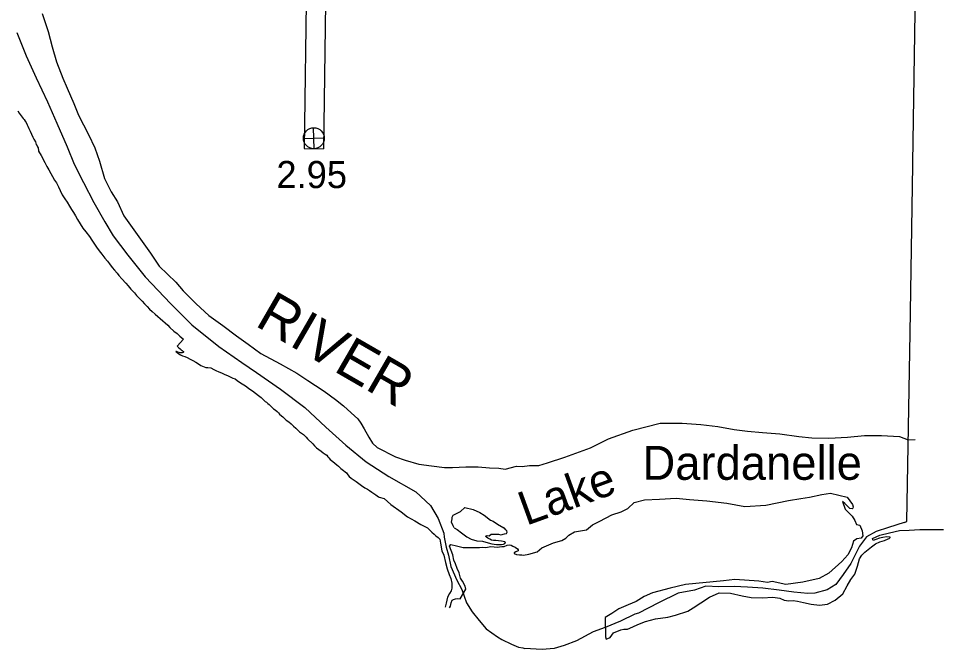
# Model space of a CAD drawing. Extents: x -939622 to -934245, y 1383184 to 1385301.
# Drawn here: x -936165.29 to -936122.1, y 1384575.76 to 1384605.22 of the extents above; entities that cross this region are included whole.
import ezdxf

# ---------------------------------------------------------------- set-up
doc = ezdxf.new("R2010")
doc.units = 0
for name, color, linetype in [('Level 10', 7, 'Continuous'), ('Level 2', 7, 'Continuous'), ('Level 25', 7, 'Continuous'), ('Level 26', 7, 'Continuous'), ('Level 9', 7, 'Continuous')]:
    doc.layers.add(name, color=color, linetype=linetype)

msp = doc.modelspace()

# ---------------------------------------------------------------- linework, layer by layer
at = {"layer": 'Level 10'}
for points in [[(-936149.7, 1384613.496), (-936150.055, 1384613.37), (-936150.212, 1384613.233), (-936150.433, 1384613.002), (-936150.766, 1384612.565), (-936151.072, 1384612.074), (-936151.171, 1384611.898), (-936151.238, 1384611.699), (-936151.269, 1384611.558), (-936151.633, 1384609.156), (-936151.818, 1384608.195), (-936151.844, 1384607.955), (-936151.836, 1384607.099), (-936151.951, 1384599.154)], [(-936149.134, 1384612.628), (-936149.592, 1384612.579), (-936149.748, 1384612.416), (-936150.025, 1384612.053), (-936150.297, 1384611.615), (-936150.345, 1384611.53), (-936150.37, 1384611.457), (-936150.384, 1384611.393), (-936150.745, 1384609.003), (-936150.927, 1384608.06), (-936150.944, 1384607.911), (-936150.936, 1384607.097), (-936151.051, 1384599.14)], [(-936151.951, 1384599.154), (-936151.051, 1384599.14)]]:
    msp.add_lwpolyline(points, dxfattribs=at)
at = {"layer": 'Level 2'}
for points in [[(-936123.81, 1384581.739), (-936123.664, 1384590.549), (-936123.533, 1384598.366), (-936123.535, 1384598.481), (-936123.408, 1384606.518), (-936123.297, 1384614.414), (-936123.256, 1384617.539)], [(-936165.368, 1384604.569), (-936164.93, 1384603.475), (-936164.453, 1384602.443), (-936163.928, 1384601.334), (-936163.498, 1384600.338), (-936163.015, 1384599.229), (-936162.681, 1384598.417), (-936162.252, 1384597.554), (-936161.768, 1384596.621), (-936161.249, 1384595.725), (-936160.86, 1384595.078), (-936160.182, 1384594.169), (-936159.375, 1384593.158), (-936158.176, 1384591.902), (-936157.186, 1384590.92), (-936155.932, 1384589.908), (-936154.864, 1384589.151), (-936154.175, 1384588.684), (-936153.047, 1384587.915), (-936151.919, 1384587.059), (-936150.937, 1384586.146), (-936150.001, 1384585.306), (-936149.047, 1384584.522), (-936147.993, 1384583.841), (-936146.73, 1384583.12), (-936146.057, 1384582.475), (-936145.698, 1384581.882), (-936145.426, 1384581.189)], [(-936123.934, 1384581.692), (-936124.663, 1384581.454), (-936125.24, 1384581.274), (-936125.704, 1384581.017), (-936126.016, 1384580.585), (-936126.421, 1384579.775), (-936126.785, 1384579.255), (-936127.123, 1384578.79), (-936127.525, 1384578.546), (-936128.114, 1384578.396), (-936128.44, 1384578.381), (-936129.096, 1384578.44), (-936129.766, 1384578.523), (-936130.539, 1384578.616), (-936131.245, 1384578.668), (-936131.879, 1384578.707), (-936132.595, 1384578.68), (-936133.19, 1384578.716), (-936133.731, 1384578.53), (-936134.494, 1384578.395), (-936135.411, 1384577.932), (-936136.337, 1384577.452), (-936136.508, 1384577.407), (-936137.175, 1384577.084), (-936137.9, 1384576.781), (-936138.461, 1384576.585), (-936139.241, 1384576.17), (-936139.811, 1384575.945), (-936140.274, 1384575.814), (-936140.832, 1384575.76), (-936141.658, 1384575.814)], [(-936123.934, 1384581.692), (-936123.81, 1384581.739)], [(-936145.52, 1384581.438), (-936145.426, 1384581.189), (-936145.408, 1384581.012), (-936145.317, 1384580.537), (-936145.217, 1384580.165), (-936145.105, 1384579.637), (-936144.822, 1384579.004), (-936144.593, 1384578.56), (-936144.364, 1384577.936), (-936144.103, 1384577.516), (-936143.784, 1384577.115), (-936143.45, 1384576.731), (-936142.928, 1384576.354), (-936142.715, 1384576.22), (-936142.276, 1384576.008), (-936141.94, 1384575.867), (-936141.739, 1384575.832), (-936141.658, 1384575.814)]]:
    msp.add_lwpolyline(points, dxfattribs=at)
at = {"layer": 'Level 26'}
for p, q in [((-936151.487, 1384599.14), (-936151.509, 1384600.117)), ((-936151.986, 1384599.617), (-936151.01, 1384599.64))]:
    msp.add_line(p, q, dxfattribs=at)
msp.add_circle((-936151.498, 1384599.628), 0.488, dxfattribs=at)
at = {"layer": 'Level 9'}
for points in [[(-936164.182, 1384605.455), (-936163.899, 1384604.604), (-936163.712, 1384603.898), (-936163.507, 1384603.189), (-936163.221, 1384602.431), (-936163.012, 1384601.962), (-936162.696, 1384601.246), (-936162.484, 1384600.705), (-936162.016, 1384599.797), (-936161.714, 1384599.174), (-936161.497, 1384598.555), (-936161.265, 1384597.755), (-936160.961, 1384597.133), (-936160.659, 1384596.654), (-936160.361, 1384596.005), (-936159.904, 1384595.358), (-936159.13, 1384594.268), (-936158.711, 1384593.655), (-936157.934, 1384592.902), (-936157.593, 1384592.501), (-936156.992, 1384591.89), (-936156.402, 1384591.351), (-936155.741, 1384590.881), (-936155.113, 1384590.398), (-936154.568, 1384590.009), (-936153.978, 1384589.581), (-936153.068, 1384589.089), (-936152.299, 1384588.658), (-936151.781, 1384588.314), (-936151.416, 1384588.082), (-936151.009, 1384587.82), (-936150.488, 1384587.431), (-936150.117, 1384587.138), (-936149.749, 1384586.804), (-936149.45, 1384586.521), (-936149.303, 1384586.331), (-936149.151, 1384586.061), (-936148.927, 1384585.666), (-936148.757, 1384585.393), (-936148.536, 1384585.197), (-936147.685, 1384584.747), (-936147.23, 1384584.599), (-936146.592, 1384584.417), (-936146.007, 1384584.334), (-936145.402, 1384584.255), (-936145.024, 1384584.263), (-936144.407, 1384584.294), (-936143.822, 1384584.281), (-936143.289, 1384584.24), (-936142.854, 1384584.224), (-936142.561, 1384584.181), (-936142.042, 1384584.321), (-936141.772, 1384584.308)], [(-936165.314, 1384600.907), (-936165.247, 1384600.792), (-936165.164, 1384600.674), (-936165.119, 1384600.616), (-936165.072, 1384600.556), (-936165.028, 1384600.498), (-936164.975, 1384600.422), (-936164.933, 1384600.356), (-936164.886, 1384600.25)], [(-936164.886, 1384600.25), (-936164.857, 1384600.19), (-936164.81, 1384600.081), (-936164.746, 1384599.954), (-936164.684, 1384599.818), (-936164.617, 1384599.685), (-936164.564, 1384599.589), (-936164.499, 1384599.453), (-936164.453, 1384599.338), (-936164.42, 1384599.28), (-936164.397, 1384599.229), (-936164.373, 1384599.172), (-936164.365, 1384599.136), (-936164.356, 1384599.096), (-936164.354, 1384599.063), (-936164.351, 1384599.021), (-936164.233, 1384598.822), (-936164.057, 1384598.492), (-936163.96, 1384598.314), (-936163.872, 1384598.154), (-936163.78, 1384597.987), (-936163.701, 1384597.845), (-936163.601, 1384597.676), (-936163.512, 1384597.543), (-936163.415, 1384597.355), (-936163.345, 1384597.189), (-936163.239, 1384596.99), (-936163.121, 1384596.805), (-936163.018, 1384596.636), (-936162.909, 1384596.463), (-936162.809, 1384596.297), (-936162.718, 1384596.155), (-936162.623, 1384596.009), (-936162.529, 1384595.834), (-936162.408, 1384595.628), (-936162.275, 1384595.435), (-936162.142, 1384595.256), (-936161.971, 1384595.041), (-936161.865, 1384594.865), (-936161.776, 1384594.735), (-936161.64, 1384594.538), (-936161.516, 1384594.375), (-936161.392, 1384594.223), (-936161.25, 1384594.035), (-936161.135, 1384593.881), (-936161.037, 1384593.76), (-936160.91, 1384593.599), (-936160.803, 1384593.469), (-936160.685, 1384593.326), (-936160.599, 1384593.22), (-936160.454, 1384593.071), (-936160.276, 1384592.862), (-936160.163, 1384592.744), (-936160.036, 1384592.589), (-936159.965, 1384592.507), (-936159.876, 1384592.404), (-936159.775, 1384592.289), (-936159.63, 1384592.14), (-936159.514, 1384592.025), (-936159.399, 1384591.9), (-936159.283, 1384591.779), (-936159.164, 1384591.651), (-936159.049, 1384591.533), (-936158.909, 1384591.414), (-936158.778, 1384591.308), (-936158.668, 1384591.219), (-936158.321, 1384590.894), (-936158.22, 1384590.794), (-936158.027, 1384590.627), (-936157.881, 1384590.505), (-936157.76, 1384590.389), (-936157.661, 1384590.31), (-936157.581, 1384590.252), (-936157.885, 1384589.919), (-936157.804, 1384589.846), (-936157.745, 1384589.791), (-936157.691, 1384589.748), (-936157.644, 1384589.715), (-936157.611, 1384589.69), (-936157.587, 1384589.666), (-936157.585, 1384589.654), (-936157.585, 1384589.639), (-936157.603, 1384589.624), (-936157.642, 1384589.613), (-936157.678, 1384589.61), (-936157.732, 1384589.61), (-936157.783, 1384589.626), (-936157.846, 1384589.645), (-936157.908, 1384589.678), (-936157.938, 1384589.679), (-936157.929, 1384589.661), (-936157.873, 1384589.621), (-936157.798, 1384589.566), (-936157.718, 1384589.52), (-936157.631, 1384589.477), (-936157.515, 1384589.434), (-936157.405, 1384589.385), (-936157.267, 1384589.314), (-936157.154, 1384589.256), (-936157.005, 1384589.173), (-936156.88, 1384589.091)], [(-936156.88, 1384589.091), (-936156.773, 1384589.021), (-936156.62, 1384588.959), (-936156.537, 1384588.928), (-936156.45, 1384588.927), (-936156.303, 1384588.902), (-936156.169, 1384588.837), (-936156.067, 1384588.788), (-936155.93, 1384588.726), (-936155.814, 1384588.677), (-936155.656, 1384588.603), (-936155.53, 1384588.545), (-936155.396, 1384588.486), (-936155.282, 1384588.434), (-936155.172, 1384588.388), (-936155.074, 1384588.321), (-936154.925, 1384588.214), (-936154.687, 1384588.064), (-936154.547, 1384587.955), (-936154.437, 1384587.878), (-936154.368, 1384587.833), (-936154.074, 1384587.625), (-936153.952, 1384587.528), (-936153.863, 1384587.434), (-936153.777, 1384587.343), (-936153.711, 1384587.306), (-936153.64, 1384587.251), (-936153.589, 1384587.202), (-936153.551, 1384587.166), (-936153.521, 1384587.139), (-936153.506, 1384587.12), (-936153.48, 1384587.084), (-936153.45, 1384587.063), (-936153.382, 1384587.002), (-936153.301, 1384586.944), (-936153.206, 1384586.871), (-936153.141, 1384586.801), (-936153.108, 1384586.753), (-936153.01, 1384586.673), (-936152.945, 1384586.616), (-936152.856, 1384586.534), (-936152.782, 1384586.47), (-936152.668, 1384586.384), (-936152.561, 1384586.296), (-936152.443, 1384586.184), (-936152.345, 1384586.096), (-936152.238, 1384585.992), (-936152.164, 1384585.928), (-936152.08, 1384585.864), (-936151.985, 1384585.794), (-936151.899, 1384585.715), (-936151.86, 1384585.67), (-936151.801, 1384585.597), (-936151.549, 1384585.354), (-936151.469, 1384585.269), (-936151.368, 1384585.181), (-936151.264, 1384585.089), (-936151.163, 1384585.019), (-936151.059, 1384584.946), (-936150.966, 1384584.882), (-936150.898, 1384584.827), (-936150.839, 1384584.76), (-936150.791, 1384584.7), (-936150.732, 1384584.636), (-936150.616, 1384584.533), (-936150.515, 1384584.46), (-936150.42, 1384584.386), (-936150.352, 1384584.32), (-936150.236, 1384584.213), (-936150.111, 1384584.119), (-936150.036, 1384584.061), (-936149.977, 1384584), (-936149.918, 1384583.915), (-936149.85, 1384583.837), (-936149.749, 1384583.754), (-936149.621, 1384583.666), (-936149.526, 1384583.608), (-936149.401, 1384583.516), (-936149.27, 1384583.419), (-936149.112, 1384583.3), (-936148.996, 1384583.239), (-936148.897, 1384583.18), (-936148.79, 1384583.107), (-936148.701, 1384583.043), (-936148.606, 1384582.988), (-936148.537, 1384582.936), (-936148.472, 1384582.885), (-936148.445, 1384582.866), (-936148.216, 1384582.809)], [(-936141.772, 1384584.308), (-936141.437, 1384584.356), (-936140.995, 1384584.349), (-936140.583, 1384584.475), (-936139.776, 1384584.741), (-936138.585, 1384585.175), (-936137.737, 1384585.6), (-936136.611, 1384586.005), (-936135.328, 1384586.324), (-936134.298, 1384586.33), (-936133.431, 1384586.26), (-936132.639, 1384586.165), (-936131.877, 1384586.035), (-936131.25, 1384585.955), (-936130.548, 1384585.894), (-936129.738, 1384585.824), (-936128.85, 1384585.699), (-936128.249, 1384585.646), (-936127.448, 1384585.621), (-936126.585, 1384585.676), (-936125.786, 1384585.753), (-936125.002, 1384585.758), (-936124.161, 1384585.703), (-936123.757, 1384585.552), (-936123.43, 1384585.558)], [(-936148.216, 1384582.809), (-936147.906, 1384582.537), (-936147.415, 1384582.193), (-936147.131, 1384581.955), (-936146.775, 1384581.768), (-936146.508, 1384581.593), (-936146.185, 1384581.436)], [(-936138.77, 1384581.351), (-936138.495, 1384581.58), (-936138.151, 1384581.746), (-936137.581, 1384582.05), (-936137.156, 1384582.182), (-936136.845, 1384582.35), (-936136.548, 1384582.63), (-936136.061, 1384582.74), (-936135.363, 1384582.785), (-936134.588, 1384582.832), (-936133.964, 1384582.769), (-936133.151, 1384582.696), (-936132.224, 1384582.586), (-936131.375, 1384582.431), (-936130.398, 1384582.504), (-936129.345, 1384582.711), (-936128.768, 1384582.811), (-936128.356, 1384582.867), (-936127.778, 1384583), (-936127.372, 1384583.054), (-936126.599, 1384582.87), (-936126.356, 1384582.531), (-936126.321, 1384582.413), (-936126.333, 1384582.356), (-936126.369, 1384582.333), (-936126.471, 1384582.346), (-936126.707, 1384582.576), (-936126.814, 1384582.673), (-936126.691, 1384582.309), (-936126.37, 1384581.987), (-936126.242, 1384581.776), (-936126.169, 1384581.592)], [(-936144.953, 1384581.439), (-936144.995, 1384581.541), (-936145.069, 1384581.701), (-936145.042, 1384581.86), (-936145.039, 1384581.911), (-936145.036, 1384581.944), (-936144.996, 1384582.037), (-936144.831, 1384582.115), (-936144.657, 1384582.204), (-936144.444, 1384582.39), (-936144.067, 1384582.302), (-936143.755, 1384582.151), (-936143.546, 1384582.024), (-936143.243, 1384581.801), (-936143.133, 1384581.747), (-936142.917, 1384581.608), (-936142.62, 1384581.445)], [(-936126.169, 1384581.592), (-936126.009, 1384581.562), (-936125.897, 1384581.305), (-936125.867, 1384581.068), (-936125.952, 1384580.962), (-936126.144, 1384580.923), (-936126.307, 1384580.818), (-936126.39, 1384580.51), (-936126.568, 1384580.173), (-936126.848, 1384579.865), (-936127.458, 1384579.326), (-936127.911, 1384579.072), (-936128.661, 1384578.907), (-936129.458, 1384578.802), (-936130.093, 1384578.93), (-936130.318, 1384578.893), (-936130.73, 1384578.944), (-936131.839, 1384579.035), (-936132.378, 1384578.966), (-936134.152, 1384578.8), (-936134.87, 1384578.627), (-936135.685, 1384578.4), (-936136.07, 1384578.241), (-936136.451, 1384578.006), (-936136.827, 1384577.85), (-936137.259, 1384577.663), (-936137.592, 1384577.438), (-936137.895, 1384577.256), (-936137.879, 1384576.354), (-936137.856, 1384576.24), (-936137.668, 1384576.327), (-936137.503, 1384576.54), (-936137.172, 1384576.678), (-936137.019, 1384576.704), (-936136.851, 1384576.71), (-936136.598, 1384576.825), (-936136.372, 1384576.931), (-936136.019, 1384577.063), (-936135.553, 1384577.196), (-936134.969, 1384577.269), (-936134.616, 1384577.358), (-936134.043, 1384577.554), (-936133.787, 1384577.705), (-936133.437, 1384577.942), (-936133.027, 1384578.207), (-936132.576, 1384578.413), (-936132.045, 1384578.391), (-936131.503, 1384578.258), (-936131.076, 1384578.193), (-936130.553, 1384578.177), (-936130.076, 1384578.205), (-936129.745, 1384578.15), (-936129.546, 1384578.057), (-936129.321, 1384578.037), (-936129.117, 1384578.052), (-936128.912, 1384578.022), (-936128.632, 1384577.948), (-936128.286, 1384577.882), (-936127.895, 1384577.831), (-936127.524, 1384577.882), (-936127.163, 1384578.068), (-936126.804, 1384578.353), (-936126.594, 1384578.732), (-936126.424, 1384579.021), (-936126.236, 1384579.27), (-936126.122, 1384579.645), (-936126.019, 1384579.992), (-936125.922, 1384580.165), (-936125.774, 1384580.306), (-936125.466, 1384580.548), (-936125.279, 1384580.699), (-936125.079, 1384580.786), (-936124.858, 1384580.85), (-936124.691, 1384580.924), (-936124.641, 1384580.946), (-936124.596, 1384580.986), (-936124.587, 1384581.01), (-936124.765, 1384581.022), (-936124.929, 1384580.987), (-936125.097, 1384580.957), (-936125.264, 1384580.894), (-936125.383, 1384580.856), (-936125.412, 1384580.937), (-936125.069, 1384581.102), (-936124.626, 1384581.211), (-936124.157, 1384581.312), (-936123.698, 1384581.334), (-936123.203, 1384581.369), (-936122.888, 1384581.362), (-936122.546, 1384581.355), (-936122.102, 1384581.356)], [(-936146.185, 1384581.436), (-936145.987, 1384581.235), (-936145.882, 1384581.151), (-936145.807, 1384581.071), (-936145.699, 1384580.984), (-936145.623, 1384580.912), (-936145.587, 1384580.717), (-936145.517, 1384580.372), (-936145.433, 1384580.159), (-936145.345, 1384579.814), (-936145.267, 1384579.525), (-936145.182, 1384579.261), (-936145.104, 1384579.075), (-936145.056, 1384578.862), (-936145.055, 1384578.619), (-936145.088, 1384578.496), (-936145.16, 1384578.373), (-936145.255, 1384578.198), (-936145.327, 1384577.925), (-936145.365, 1384577.739)], [(-936144.953, 1384581.439), (-936144.803, 1384581.367), (-936144.611, 1384581.212), (-936144.352, 1384581.02), (-936144.16, 1384580.915), (-936143.893, 1384580.838), (-936143.62, 1384580.818), (-936143.359, 1384580.737), (-936143.191, 1384580.699), (-936142.975, 1384580.66), (-936142.834, 1384580.66), (-936142.729, 1384580.664), (-936142.645, 1384580.679), (-936142.582, 1384580.706), (-936142.544, 1384580.757), (-936142.583, 1384580.793), (-936142.739, 1384580.82), (-936142.874, 1384580.838), (-936142.994, 1384580.846), (-936143.11, 1384580.846), (-936143.203, 1384580.87), (-936143.285, 1384580.912), (-936143.381, 1384580.962), (-936143.438, 1384581.001), (-936143.489, 1384581.052), (-936143.411, 1384581.079), (-936143.312, 1384581.074), (-936143.219, 1384581.152), (-936143.105, 1384581.143), (-936143.033, 1384581.143), (-936142.88, 1384581.138), (-936142.763, 1384581.117), (-936142.589, 1384581.16), (-936142.505, 1384581.181), (-936142.467, 1384581.235), (-936142.494, 1384581.298), (-936142.536, 1384581.343), (-936142.599, 1384581.418), (-936142.62, 1384581.445)], [(-936141.715, 1384580.168), (-936141.466, 1384580.211), (-936141.065, 1384580.316), (-936140.852, 1384580.503), (-936140.315, 1384580.743), (-936139.927, 1384580.845), (-936139.733, 1384580.953), (-936139.6, 1384581.097), (-936139.323, 1384581.246), (-936138.77, 1384581.351)], [(-936145.17, 1384577.703), (-936145.12, 1384577.778), (-936145.09, 1384577.937), (-936145.033, 1384578.061), (-936144.97, 1384578.1), (-936144.877, 1384578.127), (-936144.778, 1384578.148), (-936144.667, 1384578.125), (-936144.407, 1384578.576), (-936144.426, 1384578.72), (-936144.558, 1384578.945), (-936144.648, 1384579.095), (-936144.715, 1384579.341), (-936144.811, 1384579.539), (-936144.884, 1384579.761), (-936144.959, 1384579.938), (-936145.016, 1384580.178), (-936145.092, 1384580.388), (-936145.164, 1384580.586), (-936145.107, 1384580.658), (-936144.831, 1384580.599), (-936144.522, 1384580.527), (-936144.15, 1384580.519), (-936143.758, 1384580.529), (-936143.632, 1384580.538), (-936143.467, 1384580.521), (-936143.236, 1384580.566), (-936143.083, 1384580.546), (-936142.933, 1384580.537), (-936142.717, 1384580.562), (-936142.615, 1384580.571), (-936142.474, 1384580.637), (-936142.363, 1384580.644), (-936142.291, 1384580.635), (-936142.207, 1384580.59), (-936142.105, 1384580.53), (-936141.994, 1384580.455), (-936141.952, 1384580.413), (-936141.964, 1384580.365), (-936142.066, 1384580.32), (-936142.147, 1384580.269), (-936142.147, 1384580.239), (-936142.039, 1384580.194), (-936141.889, 1384580.179), (-936141.793, 1384580.18), (-936141.715, 1384580.168)]]:
    msp.add_lwpolyline(points, dxfattribs=at)

# ---------------------------------------------------------------- texts
at = {"layer": 'Level 25'}
msp.add_text('2.95', height=1.2672, dxfattribs=at).set_placement((-936153.246, 1384597.299))
at = {"layer": 'Level 9'}
for s, height, rotation, p in [('RIVER', 1.9008, 330, (-936154.297, 1384590.906)), ('Lake', 1.584, 20, (-936141.584, 1384581.529))]:
    msp.add_text(s, height=height, rotation=rotation, dxfattribs=at).set_placement(p)
msp.add_text('Dardanelle', height=1.584, dxfattribs=at).set_placement((-936136.156, 1384583.682))

doc.saveas('drawing.dxf')
